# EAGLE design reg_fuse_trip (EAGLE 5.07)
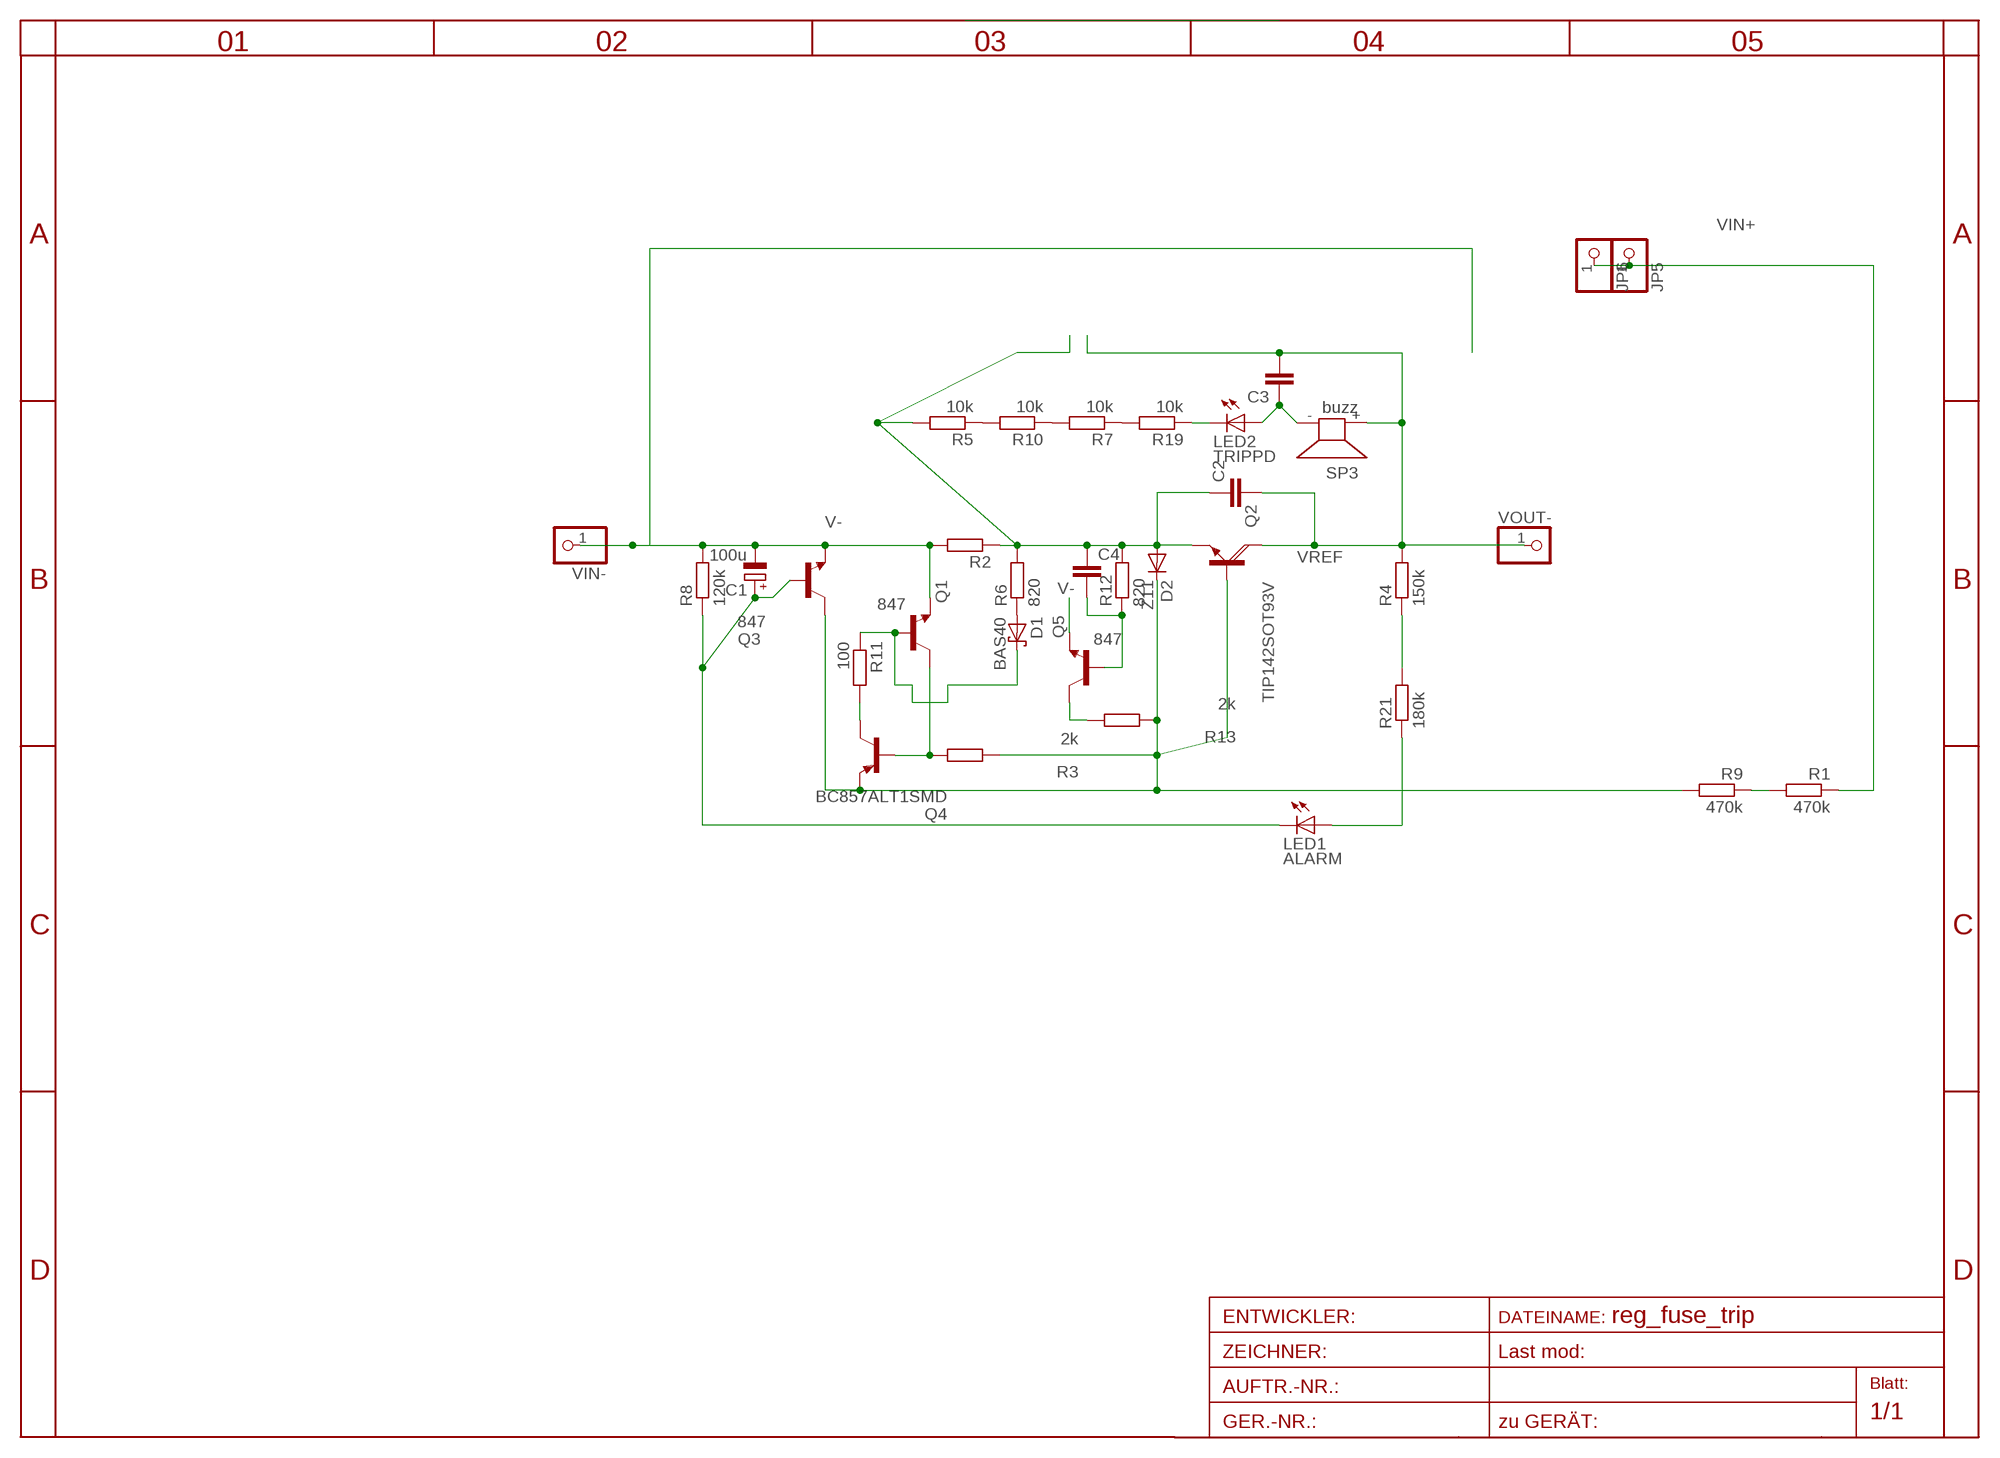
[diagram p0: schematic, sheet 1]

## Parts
C1  100u  CPOL-EUE2.5-5  [E2,5-5]
C2  C-EU225-062X268  [C225-062X268]
C3  C-EUC1206  [C1206]
C4  C-EUC1206  [C1206]
D1  BAS40  [SOT23]
D2  Z11  DIODE-D-12.5  [D-12.5]
JP5  PINHD-1X12MM3  [1X2MM3]
JP6  PINHD-1X12MM3  [1X2MM3]
LED1  ALARM  LED5MM  [LED5MM]
LED2  TRIPPD  LED5MM  [LED5MM]
Q1  847  BC847ALT1SMD  [SOT23]
Q2  TIP142SOT93V  [SOT93V]
Q3  847  BC847ALT1SMD  [SOT23]
Q4  BC857ALT1SMD  [SOT23-BEC]
Q5  847  BC847ALT1SMD  [SOT23]
R1  470k  R-EU_R1206  [R1206]
R2  R-EU_0411/12  [0411/12]
R3  2k  R-EU_R0805  [R0805]
R4  150k  R-EU_R1206  [R1206]
R5  10k  R-EU_R1206  [R1206]
R6  820  R-EU_R1206  [R1206]
R7  10k  R-EU_R1206  [R1206]
R8  120k  R-EU_R0805  [R0805]
R9  470k  R-EU_R1206  [R1206]
R10  10k  R-EU_R1206  [R1206]
R11  100  R-EU_R0805  [R0805]
R12  820  R-EU_R1206  [R1206]
R13  2k  R-EU_R0805  [R0805]
R19  10k  R-EU_R1206  [R1206]
R21  180k  R-EU_R1206  [R1206]
SP3  buzz  KSS12017MM  [KSS1202]
VIN-  PINHD-1X12MM3  [1X2MM3]
VOUT-  PINHD-1X12MM3  [1X2MM3]

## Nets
A1: C3.1 LED2.A SP3.-
E1: C2.1 C4.1 D2.A Q2.E R2.1 R5.2 R6.2 R12.2
GATE: D2.C Q2.B Q3.3(C) Q4.E R3.1 R9.2 R13.1
N$1: R7.2 R10.1
N$2: R5.1 R10.2
N$3: Q4.C R11.2
N$4: C4.2 Q5.1(B) R12.1
N$5: Q5.3(C) R13.2
N$6: D1.3(C) Q1.1(B) R11.1
N$7: Q1.3(C) Q4.B R3.2
N$8: D1.1(A) R6.1
N$9: LED2.K(C) R19.1
N$11: LED1.A R21.1
N$20: R1.2 R9.1
N$21: R7.1 R19.2
N$22: R4.1 R21.2
SIGN: C1.+ LED1.K(C) Q3.1(B) R8.1
V-: C1.- Q1.2(E) Q3.2(E) Q5.2(E) R2.2 R8.2 VIN-.1
VIN+: JP5.1 JP6.1 R1.1
VREF: C2.2 C3.2 Q2.C R4.2 SP3.+ VOUT-.1

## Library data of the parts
C1 = rcl:CPOL-EU: POLARIZED CAPACITOR, European symbol
C2-C4 = rcl:C-EU: CAPACITOR, European symbol
D1 = diode:BAS40: Silicon Schottky Diodes
D2 = diode:DIODE-: DIODE
JP5 JP6 VIN- VOUT- = pinhead:PINHD-1X1: PIN HEADER
LED1 LED2 = led:LED: LED
Q1 Q3 Q5 = transistor-npn:BC847*: NPN Transistor
Q2 = transistor-power:TIP142: NPN DARLINGTON TRANSISTOR
Q4 = transistor-pnp:BC857*: PNP Transistror
R1 R3-R13 R19 R21 = rcl:R-EU_: RESISTOR, European symbol
R2 = rcl-2:R-EU_: RESISTOR, European symbol
SP3 = buzzer:KSS1201: SPEAKER

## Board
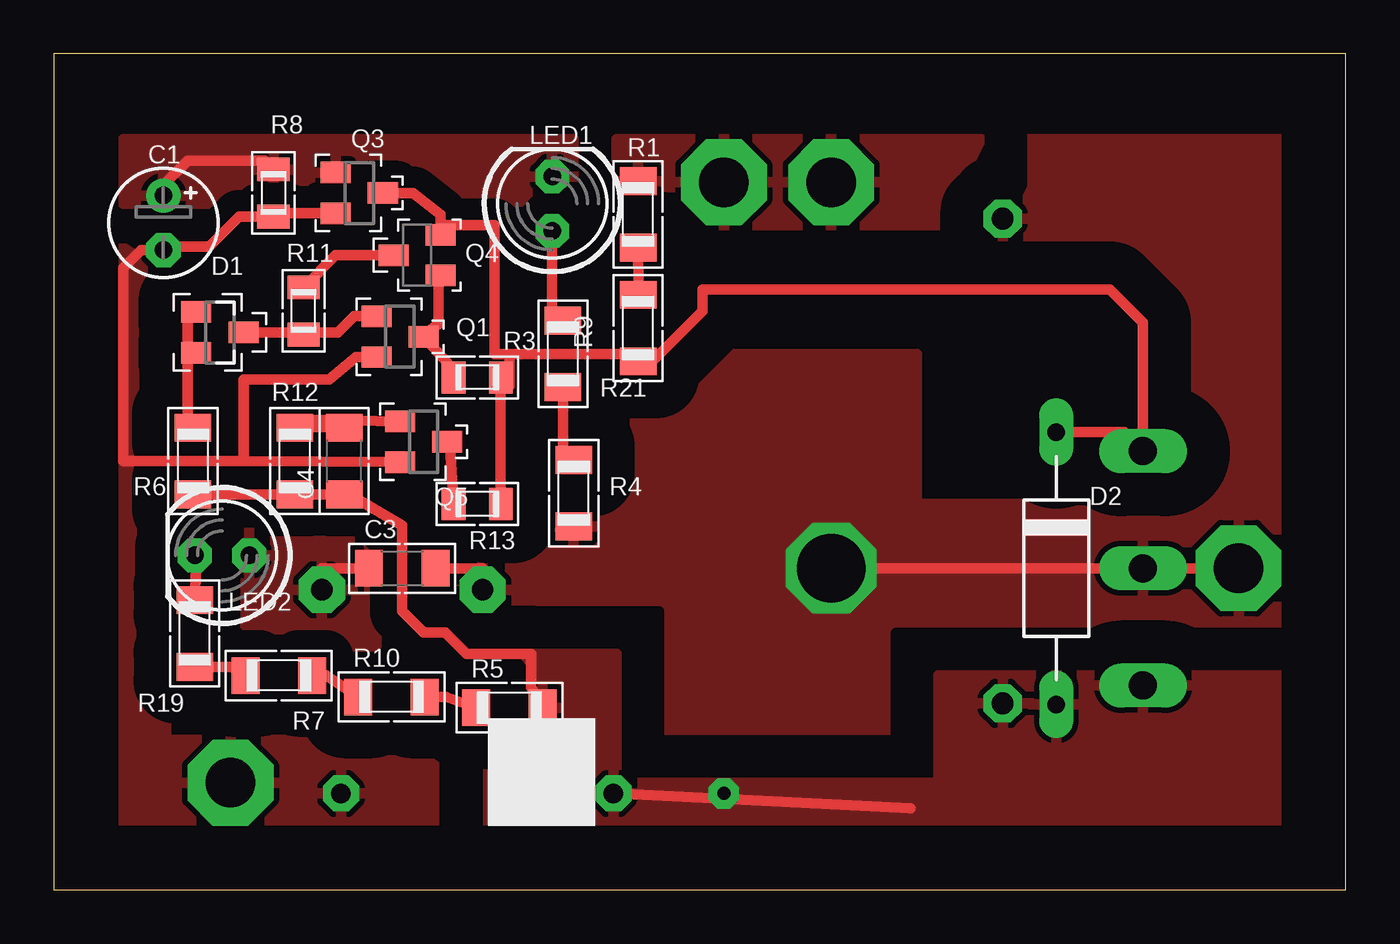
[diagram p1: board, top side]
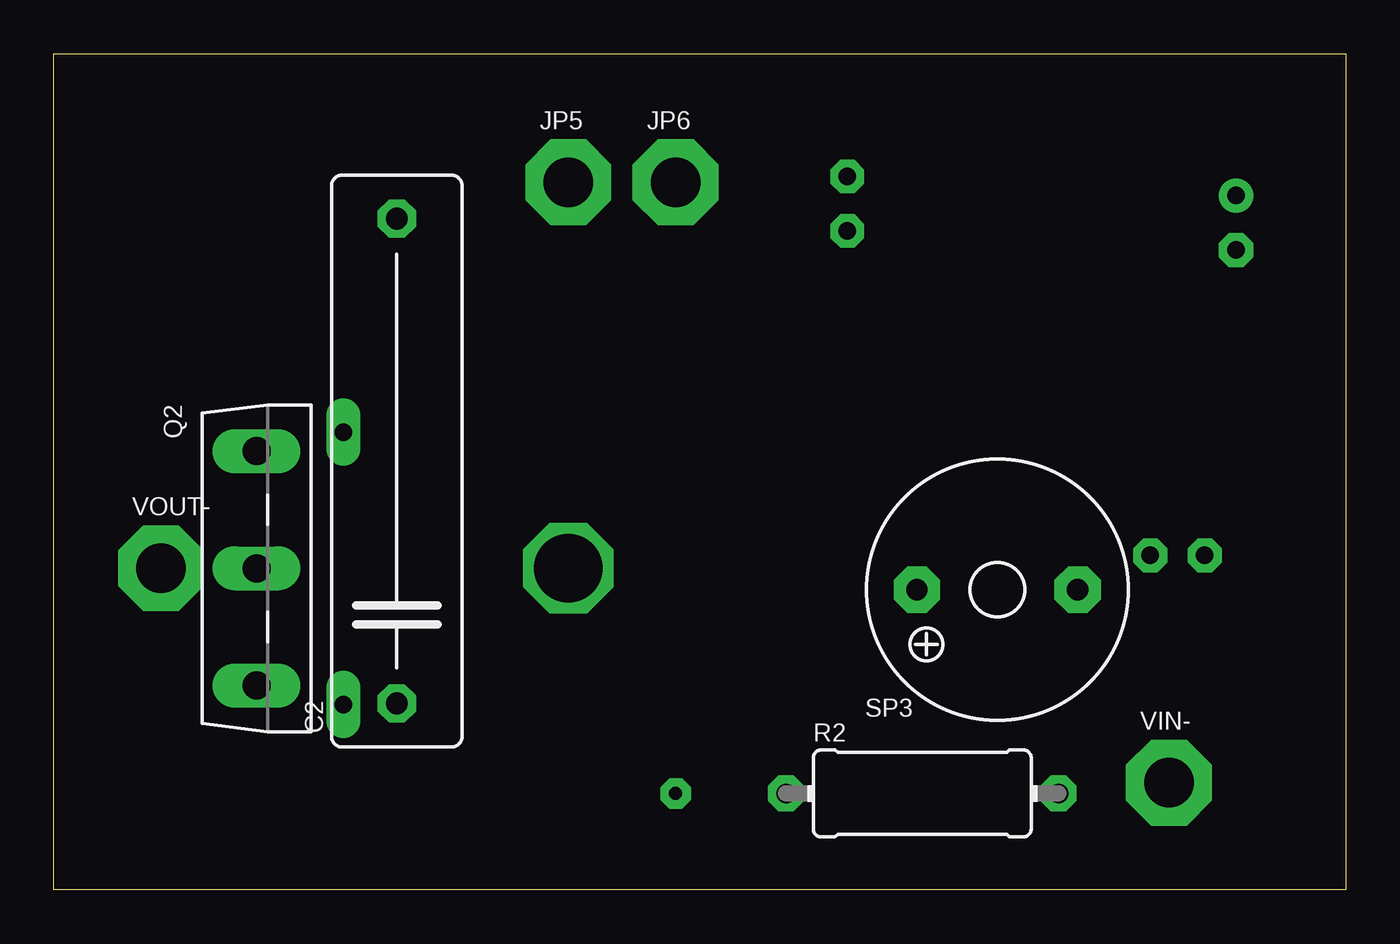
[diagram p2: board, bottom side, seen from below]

Size 60.25 x 39 mm. Coordinates in mm from the lower left corner, seen from the top.
Outline: 60.25,0 60.25,39 0,39 0,0 60.25,0
Copper layers (1*16): Top 0.035mm / dielectric 1.5mm / Bottom 0.035mm
Design rules "default *": minimum track width 10mil, minimum drill 2mil, track to track 8mil, track to pad 8mil, pad to pad 8mil, via to via 8mil, smd to smd 8mil, copper to edge 3mm, drill to drill 8mil, minimum pad ring 15mil, minimum via ring 15mil, stop-mask expansion 4mil, vias tented up to drill 0mil, thermal gap 10mil

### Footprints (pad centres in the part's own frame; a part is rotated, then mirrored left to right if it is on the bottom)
E2,5-5 = drill 0.813 pad 1.6 round: + -1.27,0 | drill 0.813 pad 1.6 octagon: - 1.27,0
C225-062X268 = drill 1.016 octagon: 1 -11.303,0; 2 11.303,0
C1206 = smd 1.3 x 1.7: 1 -1.55,0; 2 1.55,0
SOT23 = smd 1 x 1.4: 1 -0.95,-1.1; 2 0.95,-1.1; 3 0,1.1
D-12.5 = drill 0.813 long: A 6.35,0; C -6.35,0
1X2MM3 = drill 2.3 pad 4 octagon: 1 0,0
LED5MM = drill 0.813 octagon: A -1.27,0; K 1.27,0
SOT93V = drill 1.3 pad 1.676 long: B -5.461,-2.54; C 0,-2.54; E 5.461,-2.54
SOT23-BEC = smd 1 x 1.4: B -0.95,-1.1; C 0,1.1; E 0.95,-1.1
R1206 = smd 1.3 x 1.7: 1 -1.55,0; 2 1.55,0
0411/12 = drill 0.914 octagon: 1 -6.35,0; 2 6.35,0
R0805 = smd 1.1 x 1.5: 1 -1.1,0; 2 1.1,0
KSS1202 = drill 1 pad 2.159 octagon: + 3.75,0; - -3.75,0

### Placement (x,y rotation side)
C1  5.12,31.11 270 top
C2  44.25,20 90 bottom
C3  16.25,15 0 top
C4  13.55,20 90 top
D1  7.75,26 270 top
D2  46.75,15 270 top
JP5  36.25,33 0 bottom
JP6  31.25,33 0 bottom
LED1  23.25,32 90 top
LED2  7.85,15.6 180 top
Q1  16.15,25.8 270 top
Q2  48.25,15 270 bottom
Q3  14.25,32.5 270 top
Q4  16.95,29.6 90 top
Q5  17.25,20.9 270 top
R1  27.25,31.5 270 top
R2  19.75,4.5 0 bottom
R3  19.75,23.9 180 top
R4  24.25,18.5 270 top
R5  21.25,8.5 0 top
R6  6.5,20 270 top
R7  10.5,10 0 top
R8  10.25,32.5 270 top
R9  27.25,26.2 270 top
R10  15.75,9 0 top
R11  11.65,27 90 top
R12  11.25,20 270 top
R13  19.75,18 180 top
R19  6.58,11.96 270 top
R21  23.75,25 270 top
SP3  16.25,14 180 bottom
VIN-  8.25,5 0 bottom
VOUT-  55.25,15 0 bottom

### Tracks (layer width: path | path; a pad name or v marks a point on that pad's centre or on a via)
A1
  Top 0.5: C3.1 12.5,15 SP3.-
  pour Top (isolate 1.27): 8.75,16.8 13.45,16.8 15.05,15.2 15.05,11.4 14.55,10.9 10.35,10.9 8.25,13
E1  (via drill 0.6 pad 1.42)
  Top 0.5: R2.1 39.95,3.81 | R6.2 R12.2 12.25,18.45 C4.1 13.8,18.45 16.25,17 16.25,13 17.25,12 18.25,12 19.25,11 22.25,11 22.25,9.45 R5.2
  other vias: 31.25,4.5
  pour Top (isolate 2, rank 2): 18.25,11 18.25,8 19.25,8 20.25,7 20.25,2 57.25,2 57.25,10 41.25,10 41.25,5 26.25,5 26.25,11
GATE
  Top 0.5: Q3.3 16.75,32.5 18.05,31.5 Q4.E | Q4.E 18.4,30.85 | D2.C 49.9,21.35 Q2.B 50.79,26.46 49.25,28 30.25,28 30.25,27 27.9,24.65 R9.2 26.9,25 21.25,25 | 21.25,25 20.55,25 20.55,31 18.05,31 Q4.E | R13.1 R3.1 21.25,23.5 21.25,25
N$1
  Top 0.5: R7.2 12.7,10 R10.1
N$2
  Top 0.5: R10.2 18.3,9 R5.1
N$3
  Top 0.5: Q4.C 13.15,29.6 R11.2
N$4
  Top 0.406: C4.2 R12.1
  Top 0.5: Q5.1 10.65,21.95 R12.1
N$5
  Top 0.5: Q5.3 18.45,21 R13.2
N$6
  Top 0.5: D1.3 11.55,26 R11.1 11.75,26 13.25,26 14,26.75 Q1.1
N$7
  Top 0.5: Q4.B 17.95,28.45 17.95,26.4 Q1.3 18.35,24.6 R3.2
N$8
  Top 0.5: R6.1 6.25,21.9 6.25,26.55 D1.1
N$9
  Top 0.5: LED2.K 6.65,15.01 R19.1
N$11
  Top 0.5: LED1.A 23.25,27.05 R21.1
N$20
  Top 0.5: R9.1 27.28,27.97 R1.2
N$21
  Top 0.5: R19.2 8.29,10.41 R7.1
N$22
  Top 0.5: R21.2 23.75,20.55 R4.1
SIGN
  Top 0.5: C1.+ 5.12,32.87 6.25,34 9.85,34 R8.1
  pour Top (isolate 1, rank 2): 3.25,32 3.25,35 24.25,35 24.25,32
V-
  Top 0.5: 8.85,20 Q5.2 | Q1.2 14.1,24.85 12.85,23.8 8.85,23.8 8.85,20 | Q3.2 10.4,31.55 R8.2 8.65,31.4 7.25,30 5.28,30 C1.- 4.09,29.84 3.25,29 3.25,20 8.85,20
  pour Top (isolate 2): 2.25,31 5.25,31 5.25,7 17.75,7 17.75,1 2.25,1
VIN+
  pour Top (isolate 2): 26.25,35 43.25,35 41.25,31 26.25,31
VREF  (via drill 3.2 pad 3.81)
  Top 0.5: C3.2 20,15 SP3.+ | v36.25,15 Q2.C VOUT-.1 v36.25,15
  pour Top (isolate 2, rank 4): 43.25,35 58.25,35 57.25,12 41.25,12 41.25,7 28.25,7 28.25,12 17.25,12 17.25,16 22.25,18 22.25,25 40.25,25 40.25,18 53.25,18 53.25,22 41.25,22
